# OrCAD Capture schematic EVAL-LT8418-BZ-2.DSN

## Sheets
1 PAGE1: size Custom; note: 100V HALF-BRIDGE GaN DRIVER
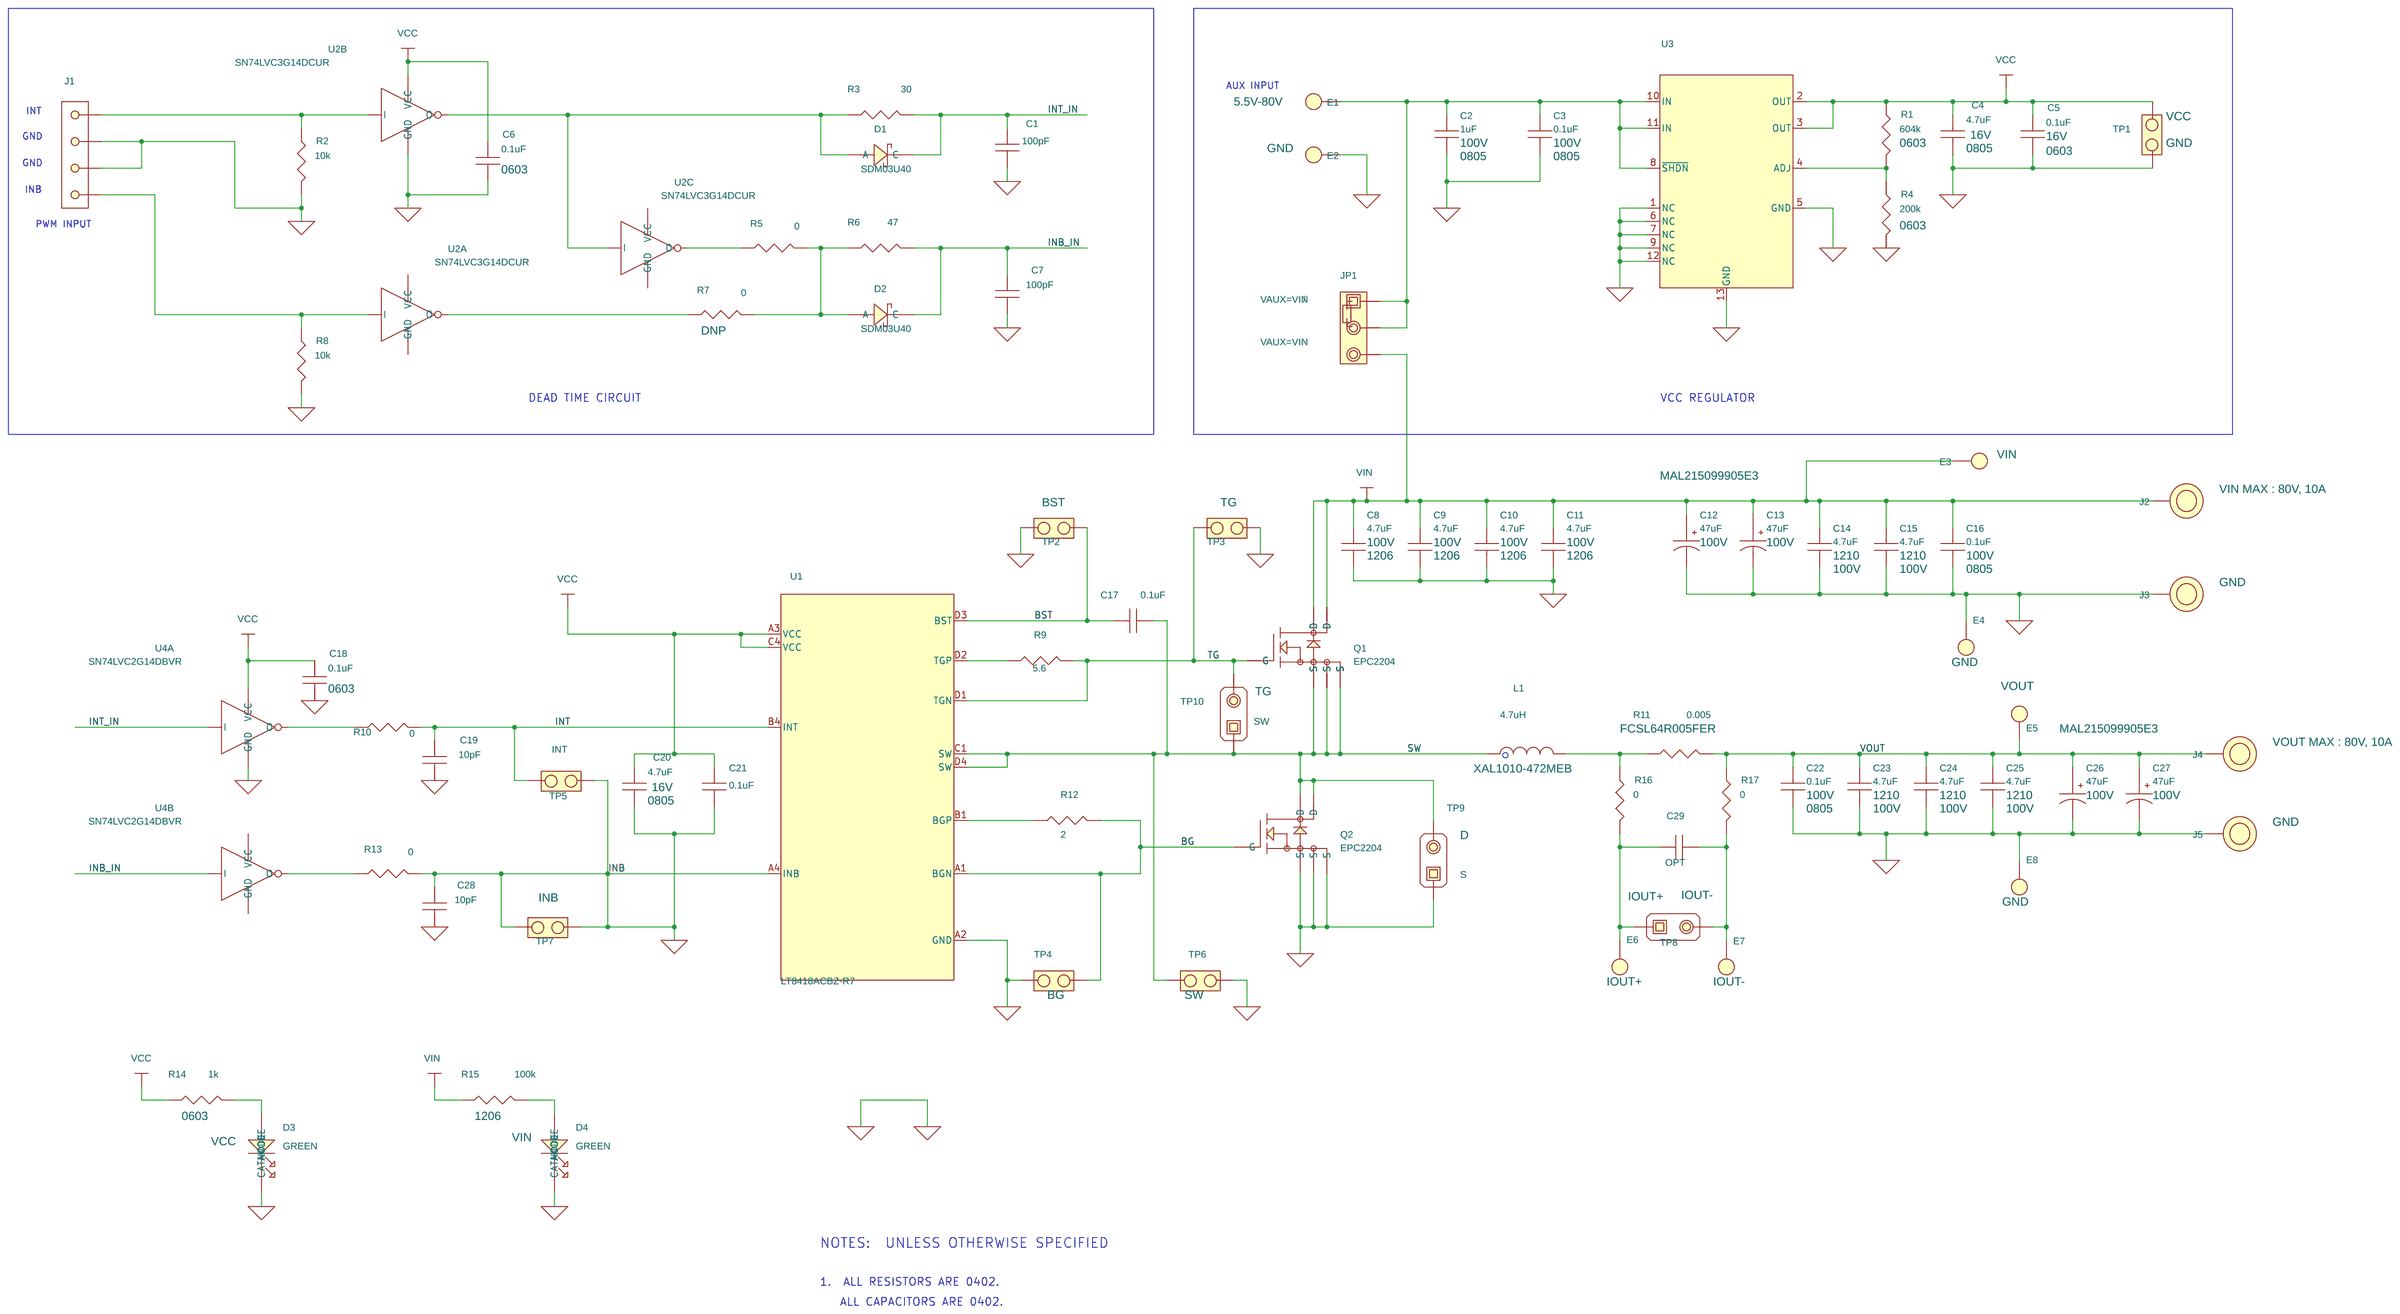
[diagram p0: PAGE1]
2 PAGE2
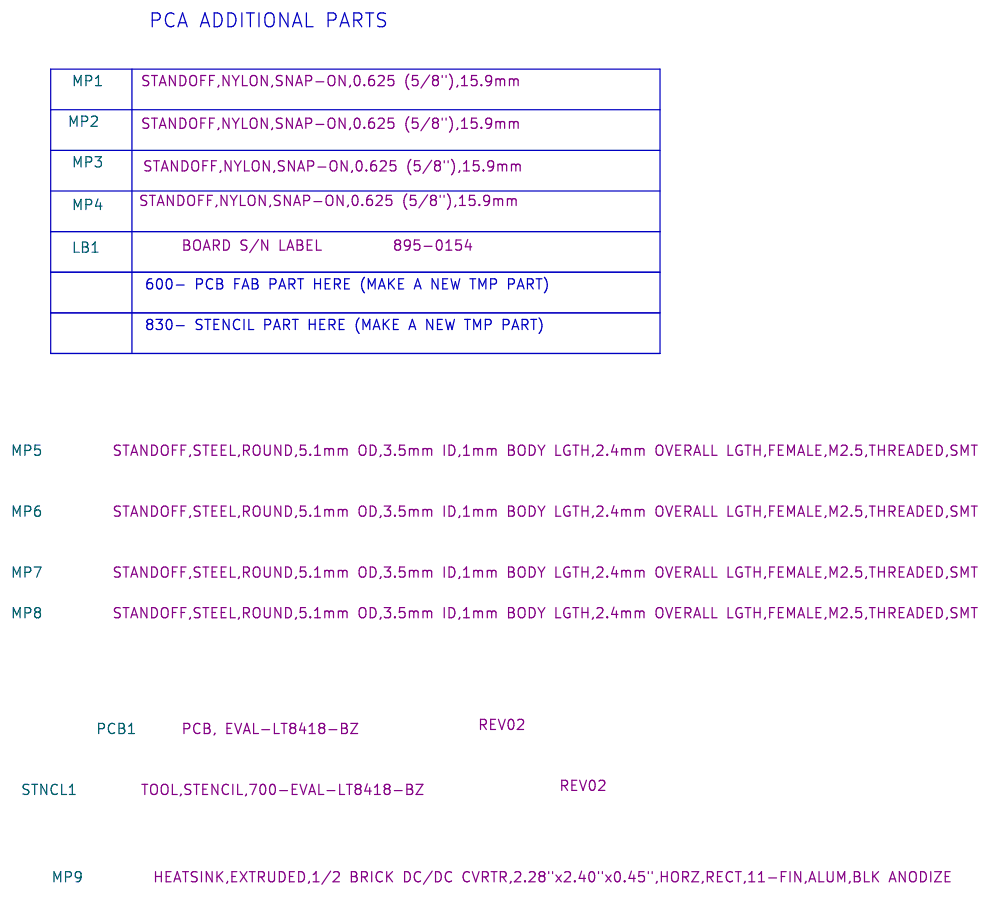
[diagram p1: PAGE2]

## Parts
sheet PAGE1
C1  100pF  [CC0402N]
C2  1uF  [CC0805N]
C3  0.1uF  [CC0805N]
C4  4.7uF  [CC0805N]
C5  0.1uF  [CC0603N]
C6  0.1uF  [CC0603N]
C7  100pF  [CC0402N]
C8  4.7uF  [CC1206N]
C9  4.7uF  [CC1206N]
C10  4.7uF  [CC1206N]
C11  4.7uF  [CC1206N]
C12  47uF  [VISHAY-CASE_CODE-1010]
C13  47uF  [VISHAY-CASE_CODE-1010]
C14  4.7uF  [CC1210N]
C15  4.7uF  [CC1210N]
C16  0.1uF  [CC0805N]
C17  0.1uF  [CC0402N]
C18  0.1uF  [CC0603N]
C19  10pF  [CC0402N]
C20  4.7uF  [CC0805N]
C21  0.1uF  [CC0402N]
C22  0.1uF  [CC0805N]
C23  4.7uF  [CC1210N]
C24  4.7uF  [CC1210N]
C25  4.7uF  [CC1210N]
C26  47uF  [VISHAY-CASE_CODE-1010]
C27  47uF  [VISHAY-CASE_CODE-1010]
C28  10pF  [CC0402N]
C29  OPT  [CC0603N]
D1  SDM03U40  [SOD-523N]
D2  SDM03U40  [SOD-523N]
D3  GREEN  [LED_0805]
D4  GREEN  [LED_0805]
E1  TEST POINT  [MILLMAX2308]
E2  TEST POINT  [MILLMAX2308]
E3  TEST POINT  [MILLMAX2308]
E4  TEST POINT  [MILLMAX2308]
E5  TEST POINT  [MILLMAX2308]
E6  TEST POINT  [MILLMAX2308]
E7  TEST POINT  [MILLMAX2308]
E8  TEST POINT  [MILLMAX2308]
J1  HDR.  [HD1X4-100]
J2  BANANA JACK  [KEY-575-4]
J3  BANANA JACK  [KEY-575-4]
J4  BANANA JACK  [KEY-575-4]
J5  BANANA JACK  [KEY-575-4]
JP1  HDR  [HD1X3-079]
L1  4.7uH  [COILCRAFT-XAL1010]
Q1  EPC2204  [EGAN-EPC2204]
Q2  EPC2204  [EGAN-EPC2204]
R1  604k  [CR0603N]
R2  10k  [CR0402N]
R3  30  [CR0402N]
R4  200k  [CR0603N]
R5  0  [CR0402N]
R6  47  [CR0402N]
R7  0  [CR0402N]
R8  10k  [CR0402N]
R9  5.6  [CR0402N]
R10  0  [CR0402N]
R11  0.005  [OHMITE-FCSL64R005FER]
R12  2  [CR0402N]
R13  0  [CR0402N]
R14  1k  [CR0603N]
R15  100k  [CR1206N]
R16  0  [CR0603N]
R17  0  [CR0603N]
TP1  HDR,SOCKET  [MILL-MAX-310-43-102-41-105000]
TP2  HDR,SOCKET  [MILL-MAX-310-43-102-41-105000]
TP3  HDR,SOCKET  [MILL-MAX-310-43-102-41-105000]
TP4  HDR,SOCKET  [MILL-MAX-310-43-102-41-105000]
TP5  HDR,SOCKET  [MILL-MAX-310-43-102-41-105000]
TP6  HDR,SOCKET  [MILL-MAX-310-43-102-41-105000]
TP7  HDR,SOCKET  [MILL-MAX-310-43-102-41-105000]
TP8  HDR  [SAMTEC-TSM-102-01-L-SV]
TP9  HDR  [SAMTEC-TSM-102-01-L-SV]
TP10  HDR  [SAMTEC-TSM-102-01-L-SV]
U1  LT8418ACBZ-R7  [LTC-CB-12-WLCSP]
U2  SN74LVC3G14DCUR  [TI-DCU]  (sections A,B,C)
U3  LT3012EDE  [LTC-DE-12-1695]
U4  SN74LVC2G14DBVR  [SOT23-6N]  (sections A,B)
XJP1  SHUNT
sheet PAGE2
LB1  LABEL  [895-0154_REV01]
MP1  STANDOFF  [KEYSTONE_8829-8834]
MP2  STANDOFF  [KEYSTONE_8829-8834]
MP3  STANDOFF  [KEYSTONE_8829-8834]
MP4  STANDOFF  [KEYSTONE_8829-8834]
MP5  STANDOFF,STEEL,ROUND
MP6  STANDOFF,STEEL,ROUND
MP7  STANDOFF,STEEL,ROUND
MP8  STANDOFF,STEEL,ROUND
MP9  HEATSINK,EXTRUDED
PCB1  PCB, EVAL-LT8418-BZ
STNCL1  TOOL,STENCIL

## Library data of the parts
C1 C7 = CAP: CAP.,100pF,C0G,50V,5%,0402; CLASS: DISCRETE; Dielectric Type: C0G; FPLIST: CC0402N,CC0402L,CC0402M; Inventory Qty: 62393; Manufacturer: AVX; Manufacturer PN: 04025A101JAT2A; PART_NUMBER: 150-0115; Package Size: 0402; Rated Voltage: 50V; Tolerance: 5%
C2 = CAP: CAP.,1uF,X7S,100V,10%,0805,AEC-Q200,NO SUBS. ALLOWED; CLASS: DISCRETE; Dielectric Type: X7S; FPLIST: CC0805N,CC0805L,CC0805M; Inventory Qty: 11870; Manufacturer: MURATA; Manufacturer PN: GCM21BC72A105KE36L; PART_NUMBER: 150-1770; Package Size: 0805; Rated Voltage: 100V; Temperature Coefficient: X7S; Tolerance: 10%
C3 C16 C22 = CAP: CAP.,0.1uF,X7R,100V,10%,0805; CLASS: DISCRETE; Dielectric Type: X7R; FPLIST: CC0805N,CC0805L,CC0805M; Inventory Qty: 13830; Manufacturer: AVX; Manufacturer PN: 08051C104KAT2A; PART_NUMBER: 150-3062; Package Size: 0805; Rated Voltage: 100V; Tolerance: 10%
C4 C20 = CAP: CAP.,4.7uF,X7R,16V,10%,0805; CLASS: DISCRETE; Dielectric Type: X7R; FPLIST: CC0805N,CC0805L,CC0805M; Inventory Qty: 29263; Manufacturer: AVX; Manufacturer PN: 0805YC475KAT2A; PART_NUMBER: 150-0152; Package Size: 0805; Rated Voltage: 16V; Tolerance: 10%
C5 C6 C18 = CAP: CAP.,0.1uF,X7R,16V,10%,0603; CLASS: DISCRETE; Dielectric Type: X7R; FPLIST: CC0603N,CC0603L,CC0603M; Inventory Qty: 34669; Manufacturer: MURATA; Manufacturer PN: GRM188R71C104KA01D; PART_NUMBER: 150-0018; Package Size: 0603; Package Type: SMD; Rated Voltage: 16V; Tolerance: 10%
C8-C11 = CAP: CAP.,4.7uF,X7S,100V,20%,1206; CLASS: DISCRETE; Dielectric Type: X7S; FPLIST: CC1206N,CC1206L,CC1206M; Inventory Qty: 11240; Manufacturer: AVX; Manufacturer PN: 12061Z475MAT2A; PART_NUMBER: 150-2278; Package Size: 1206; Rated Voltage: 100V; Tolerance: 20%
C12 C13 C26 C27 = CAP_P_ALT: CAP.,47uF,ALUM ELECT,100V,20%,SMD,RADIAL,1012,150 CRZ Series,AEC-Q200; CLASS: DISCRETE; Dielectric Type: ALUM ELECT; Inventory Qty: 0; Manufacturer: VISHAY; Manufacturer PN: MAL215099905E3; PART_NUMBER: 150-1879; Package Size: SMD,RADIAL,1012; Rated Voltage: 100V; Tolerance: 20%
C14 C15 C23-C25 = CAP: CAP.,4.7uF,X7S,100V,10%,1210; CLASS: DISCRETE; Dielectric Type: X7S; FPLIST: CC1210N,CC1210L,CC1210M; Inventory Qty: 8780; Manufacturer: SAMSUNG; Manufacturer PN: CL32Y475KCVZW6E; PART_NUMBER: 150-2270; Package Size: 1210; Package Type: SMD; Rated Voltage: 100V; Temperature Coefficient: X7S; Tolerance: 10%
C17 C21 = CAP: CAP.,0.1uF,X7R,16V,10%,0402; CLASS: DISCRETE; Dielectric Type: X7R; FPLIST: CC0402N,CC0402L,CC0402M; Inventory Qty: 324653; Manufacturer: AVX; Manufacturer PN: 0402YC104KAT2A; PART_NUMBER: 150-2081; Package Size: 0402; Rated Voltage: 16V; Tolerance: 10%
C19 C28 = CAP: CAP.,10pF,C0G,50V,5%,0402; CLASS: DISCRETE; Dielectric Type: C0G; FPLIST: CC0402N,CC0402L,CC0402M; Inventory Qty: 13869; Manufacturer: KEMET; Manufacturer PN: C0402C100J5GAC7867; PART_NUMBER: 150-2069; Package Size: 0402; Rated Voltage: 50V; Tolerance: 5%
C29 = CAP: CAP., OPTION, 0603; CLASS: DISCRETE; FPLIST: CC0603N,CC0603L,CC0603M; PART_NUMBER: 150-3038; Package Size: 0603; Package Type: SMD
D1 D2 = DIODE_SCHOTTKY_A: DIODE,SCHOTTKY,40V,30mA,SOD-523; CLASS: DISCRETE; Inventory Qty: 0; Manufacturer: DIODES INC.; Manufacturer PN: SDM03U40-7; Max Forward Current or Rated Power: 30mA; PART_NUMBER: 210-0555; Package Type: SOD-523; Rated Voltage or Zener Voltage: 40V
D3 = LED: LED,GREEN,WATER-CLEAR,0805; CLASS: DISCRETE; Inventory Qty: 0; Manufacturer: LITE-ON; Manufacturer PN: LTST-C170KGKT; PART_NUMBER: 270-0178; Package Type: 0805; TEXT: VCC
D4 = LED: LED,GREEN,WATER-CLEAR,0805; CLASS: DISCRETE; Inventory Qty: 0; Manufacturer: LITE-ON; Manufacturer PN: LTST-C170KGKT; PART_NUMBER: 270-0178; Package Type: 0805; TEXT: VIN
E1 = TEST_POINT_.156_MILL-MAX_2308: TEST POINT,TURRET,0.064" MTG. HOLE,PCB 0.062" THK; 4th Part Field: 5.5V-80V; CLASS: IO; FPLIST: MILLMAX2308,MILLMAX2308-2; Inventory Qty: 1142083; Manufacturer: MILL-MAX; Manufacturer PN: 2308-2-00-80-00-00-07-0; PART_NUMBER: 260-0004
E2 E4 E8 = TEST_POINT_.156_MILL-MAX_2308: TEST POINT,TURRET,0.064" MTG. HOLE,PCB 0.062" THK; 4th Part Field: GND; CLASS: IO; FPLIST: MILLMAX2308,MILLMAX2308-2; Inventory Qty: 1142083; Manufacturer: MILL-MAX; Manufacturer PN: 2308-2-00-80-00-00-07-0; PART_NUMBER: 260-0004
E3 = TEST_POINT_.156_MILL-MAX_2308: TEST POINT,TURRET,0.064" MTG. HOLE,PCB 0.062" THK; 4th Part Field: VIN; CLASS: IO; FPLIST: MILLMAX2308,MILLMAX2308-2; Inventory Qty: 1142083; Manufacturer: MILL-MAX; Manufacturer PN: 2308-2-00-80-00-00-07-0; PART_NUMBER: 260-0004
E5 = TEST_POINT_.156_MILL-MAX_2308: TEST POINT,TURRET,0.064" MTG. HOLE,PCB 0.062" THK; 4th Part Field: VOUT; CLASS: IO; FPLIST: MILLMAX2308,MILLMAX2308-2; Inventory Qty: 1142083; Manufacturer: MILL-MAX; Manufacturer PN: 2308-2-00-80-00-00-07-0; PART_NUMBER: 260-0004
E6 = TEST_POINT_.156_MILL-MAX_2308: TEST POINT,TURRET,0.064" MTG. HOLE,PCB 0.062" THK; 4th Part Field: IOUT+; CLASS: IO; FPLIST: MILLMAX2308,MILLMAX2308-2; Inventory Qty: 1142083; Manufacturer: MILL-MAX; Manufacturer PN: 2308-2-00-80-00-00-07-0; PART_NUMBER: 260-0004
E7 = TEST_POINT_.156_MILL-MAX_2308: TEST POINT,TURRET,0.064" MTG. HOLE,PCB 0.062" THK; 4th Part Field: IOUT-; CLASS: IO; FPLIST: MILLMAX2308,MILLMAX2308-2; Inventory Qty: 1142083; Manufacturer: MILL-MAX; Manufacturer PN: 2308-2-00-80-00-00-07-0; PART_NUMBER: 260-0004
J1 = HDR1X4: CONN.,HDR.,MALE,1x4,2.54mm,VERT,STR,THT; CLASS: IO; Inventory Qty: 13568; Manufacturer: SAMTEC; Manufacturer PN: TSW-104-07-L-S; PART_NUMBER: 250-0580
J2 = BANANA_KEYSTONE-575-4: CONN.,BANANA JACK,FEMALE,THT,NON-INSULATED,SWAGE,0.218"; 4th Part Field: VIN MAX : 80V, 10A; CLASS: IO; Inventory Qty: 203061; Manufacturer: KEYSTONE; Manufacturer PN: 575-4; PART_NUMBER: 250-0428
J3 J5 = BANANA_KEYSTONE-575-4: CONN.,BANANA JACK,FEMALE,THT,NON-INSULATED,SWAGE,0.218"; 4th Part Field: GND; CLASS: IO; Inventory Qty: 203061; Manufacturer: KEYSTONE; Manufacturer PN: 575-4; PART_NUMBER: 250-0428
J4 = BANANA_KEYSTONE-575-4: CONN.,BANANA JACK,FEMALE,THT,NON-INSULATED,SWAGE,0.218"; 4th Part Field: VOUT MAX : 80V, 10A; CLASS: IO; Inventory Qty: 203061; Manufacturer: KEYSTONE; Manufacturer PN: 575-4; PART_NUMBER: 250-0428
JP1 = 1X3_A: CONN.,HDR,MALE,1x3,2mm,VERT,ST,THT,NO SUBS. ALLOWED; 10th Part Field: /; 11th Part Field: VAUX=VIN; 9th Part Field: VAUX=VIN; CLASS: IO; Inventory Qty: 28997; Manufacturer: Wurth Elektronik; Manufacturer PN: 62000311121; PART_NUMBER: 250-0639
L1 = IND: IND.,4.7uH,PWR,20%,24A,5.7mOHMS,SMD,11.8x10.5x10mm,AEC-Q200; CLASS: DISCRETE; Inventory Qty: 420; Manufacturer: COILCRAFT; Manufacturer PN: XAL1010-472MEB; PART_NUMBER: 200-0382; Package Size: SMD,11.8x10.5x10mm; Tolerance: 20%
Q1 Q2 = EGAN-EPC2204: XSTR.,ENHANCEMENT-MODE GaN FET,100V,29A,2.5x1.5mm; CLASS: DISCRETE; Inventory Qty: 0; Manufacturer: EFFICIENT POWER CONVERSION; PART_NUMBER: 240-0617; Package Size: 2.5mmX1.5mm; Package Type: 2.5x1.5mm; Rated Voltage: 100V
R1 = RES: RES.,604k OHMS,1%,1/10W,0603,AEC-Q200; CLASS: DISCRETE; FPLIST: CR0603N,CR0603L,CR0603M; Inventory Qty: 36156; Manufacturer: VISHAY; Manufacturer PN: CRCW0603604KFKEA; PART_NUMBER: 100-2679; Package Size: 0603; Rated Power: 1/10W; Temperature Coefficient: 100ppm; Tolerance: 1%
R2 R8 = RES: RES.,10k OHMS,1%,1/16W,0402,AEC-Q200; CLASS: DISCRETE; FPLIST: CR0402N,CR0402L,CR0402M; Inventory Qty: 76366; Manufacturer: VISHAY; Manufacturer PN: CRCW040210K0FKED; PART_NUMBER: 100-2545; Package Size: 0402; Rated Power: 1/16W; Temperature Coefficient: 100ppm/C; Tolerance: 1%
R3 = RES: RES.,30 OHMS,1%,1/16W,0402; CLASS: DISCRETE; FPLIST: CR0402N,CR0402L,CR0402M; Inventory Qty: 0; Manufacturer: YAGEO; Manufacturer PN: RC0402FR-0730RL; PART_NUMBER: LOCAL-100-2320; Package Size: 0402; Rated Power: 1/16W; Temperature Coefficient: +/-100; Tolerance: 1%
R4 = RES: RES.,200k OHMS,1%,1/10W,0603; CLASS: DISCRETE; FPLIST: CR0603N,CR0603L,CR0603M; Inventory Qty: 116370; Manufacturer: NIC; Manufacturer PN: NRC06F2003TRF; PART_NUMBER: 100-2378; Package Size: 0603; Rated Power: 1/10W; Temperature Coefficient: 100ppm/C; Tolerance: 1%
R5 R10 R13 = RES: RES.,0 OHM,1/16W,0402; CLASS: DISCRETE; FPLIST: CR0402N,CR0402L,CR0402M; Inventory Qty: 133297; Manufacturer: NIC; Manufacturer PN: NRC04ZOTRF; PART_NUMBER: 100-0025; Package Size: 0402; Rated Power: 1/16W
R6 = RES: RES.,47 OHMS,1%,1/16W,0402; CLASS: DISCRETE; FPLIST: CR0402N,CR0402L,CR0402M; Inventory Qty: 596; Manufacturer: VISHAY; Manufacturer PN: CRCW040247R0FKED; PART_NUMBER: 100-2079; Package Size: 0402; Rated Power: 1/16W; Temperature Coefficient: +/-100PPM; Tolerance: 1%
R7 = RES: RES.,0 OHM,1/16W,0402; CLASS: DISCRETE; FPLIST: CR0402N,CR0402L,CR0402M; Inventory Qty: 133297; Manufacturer: NIC; Manufacturer PN: NRC04ZOTRF; PART_NUMBER: 100-0025; Package Size: 0402; Rated Power: 1/16W; TEXT: DNP
R9 = RES: RES.,5.6 OHMS,1%,1/16W,0402,AEC-Q200; CLASS: DISCRETE; FPLIST: CR0402N,CR0402L,CR0402M; Inventory Qty: 474; Manufacturer: VISHAY; Manufacturer PN: CRCW04025R60FNED; PART_NUMBER: 100-2872; Package Size: 0402; Rated Power: 1/16W; Temperature Coefficient: +/-200ppm; Tolerance: 1%
R11 = RES: RES.,0.005 OHM,1%,2W,2512,LONG-SIDE TERM,METAL,SENSE; CLASS: DISCRETE; Inventory Qty: 0; Manufacturer: Ohmite; Manufacturer PN: FCSL64R005FER; PART_NUMBER: 100-1789; Package Size: 2512,LONG-SIDE TERM; Rated Power: 2W; Temperature Coefficient: +/-50ppm; Tolerance: 1%
R12 = RES: RES.,2 OHMS,1%,1/16W,0402,AEC-Q200; CLASS: DISCRETE; FPLIST: CR0402N,CR0402L,CR0402M; Inventory Qty: 49260; Manufacturer: VISHAY; Manufacturer PN: CRCW04022R00FKED; PART_NUMBER: 100-1452; Package Size: 0402; Rated Power: 1/16W; Temperature Coefficient: +/-100ppm; Tolerance: 1%
R14 = RES: RES.,1k OHM,5%,1/10W,0603,AEC-Q200; CLASS: DISCRETE; FPLIST: CR0603N,CR0603L,CR0603M; Inventory Qty: 86764; Manufacturer: VISHAY; Manufacturer PN: CRCW06031K00JNEA; PART_NUMBER: 100-2534; Package Size: 0603; Rated Power: 1/10W; Temperature Coefficient: 200ppm/C; Tolerance: 5%
R15 = RES: RES.,100k OHMS,5%,1/4W,1206,AEC-Q200; CLASS: DISCRETE; FPLIST: CR1206N,CR1206L,CR1206M; Inventory Qty: 6920; Manufacturer: NIC; Manufacturer PN: NRC12J104TRF; PART_NUMBER: 100-2505; Package Size: 1206; Rated Power: 1/4W; Temperature Coefficient: 200ppm/C; Tolerance: 5%
R16 R17 = RES: RES.,0 OHM,1/10W,0603,AEC-Q200; CLASS: DISCRETE; FPLIST: CR0603N,CR0603L,CR0603M; Inventory Qty: 686486; Manufacturer: VISHAY; Manufacturer PN: CRCW06030000Z0EA; PART_NUMBER: 100-0009; Package Size: 0603; Rated Power: 1/10W
TP1 = 1X2_B: CONN.,HDR,SOCKET,RCPT,FEMALE,1x2,2.54mm,VERT,ST,SMD; 12th Part Field: GND; 9th Part Field: VCC; CLASS: IO; Inventory Qty: 0; Manufacturer: Mill-Max; Manufacturer PN: 310-43-102-41-105000; PART_NUMBER: 250-1048
TP2 = 1X2_B: CONN.,HDR,SOCKET,RCPT,FEMALE,1x2,2.54mm,VERT,ST,SMD; 12th Part Field: GND; 9th Part Field: BST; CLASS: IO; Inventory Qty: 0; Manufacturer: Mill-Max; Manufacturer PN: 310-43-102-41-105000; PART_NUMBER: 250-1048
TP3 = 1X2_B: CONN.,HDR,SOCKET,RCPT,FEMALE,1x2,2.54mm,VERT,ST,SMD; 12th Part Field: GND; 9th Part Field: TG; CLASS: IO; Inventory Qty: 0; Manufacturer: Mill-Max; Manufacturer PN: 310-43-102-41-105000; PART_NUMBER: 250-1048
TP4 = 1X2_B: CONN.,HDR,SOCKET,RCPT,FEMALE,1x2,2.54mm,VERT,ST,SMD; 12th Part Field: GND; 9th Part Field: BG; CLASS: IO; Inventory Qty: 0; Manufacturer: Mill-Max; Manufacturer PN: 310-43-102-41-105000; PART_NUMBER: 250-1048
TP5 = 1X2_B: CONN.,HDR,SOCKET,RCPT,FEMALE,1x2,2.54mm,VERT,ST,SMD; 12th Part Field: GND; 9th Part Field: INT; CLASS: IO; Inventory Qty: 0; Manufacturer: Mill-Max; Manufacturer PN: 310-43-102-41-105000; PART_NUMBER: 250-1048
TP6 = 1X2_B: CONN.,HDR,SOCKET,RCPT,FEMALE,1x2,2.54mm,VERT,ST,SMD; 12th Part Field: GND; 9th Part Field: SW; CLASS: IO; Inventory Qty: 0; Manufacturer: Mill-Max; Manufacturer PN: 310-43-102-41-105000; PART_NUMBER: 250-1048
TP7 = 1X2_B: CONN.,HDR,SOCKET,RCPT,FEMALE,1x2,2.54mm,VERT,ST,SMD; 12th Part Field: GND; 9th Part Field: INB; CLASS: IO; Inventory Qty: 0; Manufacturer: Mill-Max; Manufacturer PN: 310-43-102-41-105000; PART_NUMBER: 250-1048
TP8 = 1X2_A: CONN.,HDR,MALE,1x2,2.54mm,VERT,ST,SMD; CLASS: IO; Inventory Qty: 0; Manufacturer: SAMTEC; Manufacturer PN: TSM-102-01-L-SV; PART_FIELD_01: IOUT+; PART_FIELD_02: IOUT-; PART_NUMBER: local-250-1049
TP9 = 1X2_A: CONN.,HDR,MALE,1x2,2.54mm,VERT,ST,SMD; CLASS: IO; Inventory Qty: 0; Manufacturer: SAMTEC; Manufacturer PN: TSM-102-01-L-SV; PART_FIELD_01: S; PART_FIELD_02: D; PART_NUMBER: local-250-1049
TP10 = 1X2_A: CONN.,HDR,MALE,1x2,2.54mm,VERT,ST,SMD; CLASS: IO; Inventory Qty: 0; Manufacturer: SAMTEC; Manufacturer PN: TSM-102-01-L-SV; PART_FIELD_01: SW; PART_FIELD_02: TG; PART_NUMBER: local-250-1049
U1 = LT8418: IC,100V Half-Bridge GaN Driver,WLCSP-12; CLASS: IC; Inventory Qty: 0; Manufacturer: ANALOG DEVICES; PART_NUMBER: local-LT8418ACBZ-R7; Package Type: WLCSP-12
U2 = TI-SN74LVC3G14DCUR: IC,3CH Schmitt-Trigger Inverter,VSSOP-8; CLASS: IC; Inventory Qty: 0; Manufacturer: TEXAS INSTRUMENTS; PART_NUMBER: 280-0725; Package Size: DUC; Package Type: VSSOP-8
U3 = LT3012-DE: IC,250mA,4V to 80V LDO Linear Reg,DFN-12; CLASS: IC; Inventory Qty: 0; Manufacturer: ANALOG DEVICES; Manufacturer PN: LT3012EDE#PBF; PART_NUMBER: LT3012EDE#PBF; Package Type: DFN-12
U4 = TI-SN74LVC2G14DBVR: IC,Dual Schmitt-Trigger Inverter,SOT23-6; CLASS: IC; FPLIST: SOT23-6N,SOT23-6L,SOT23-6M; Inventory Qty: 1233; Manufacturer: TEXAS INSTRUMENTS; PART_NUMBER: 280-0080; Package Size: sot23-6; Package Type: SOT23-6
XJP1 = SHUNT_2MM_C: CONN.,SHUNT,FEMALE,2-POS,2mm; CLASS: IO; Inventory Qty: 64675; Manufacturer: Wurth Elektronik; Manufacturer PN: 60800213421; PART_NUMBER: 250-0485
LB1 = BLANK_LABEL: LABEL SPEC, DEMO BOARD SERIAL NUMBER; Inventory Qty: 0; Manufacturer: BRADY; Manufacturer PN: THT-96-717-10; PART_FIELD_01: BOARD S/N LABEL; PART_NUMBER: 895-0154
MP1-MP4 = BLANK_PINLESS_MECHANICAL_PART: STANDOFF,NYLON,SNAP-ON,0.625 (5/8"),15.9mm; CLASS: DISCRETE; FPLIST: KEYSTONE_8829-8834,KEYSTONE_8834; Inventory Qty: 185253; Manufacturer: KEYSTONE; Manufacturer PN: 8834; PART_NUMBER: 763-0013
MP5-MP8 = BLANK_MECHANICAL_PART: STANDOFF,STEEL,ROUND,5.1mm OD,3.5mm ID,1mm BODY LGTH,2.4mm OVERALL LGTH,FEMALE,M2.5,THREADED,SMT; CLASS: DISCRETE; Inventory Qty: 0; Manufacturer: WURTH ELEKTRONIK; Manufacturer PN: 9774010151R; PART_NUMBER: 763-0040; Package Size: 1MM
MP9 = BLANK_MECHANICAL_PART: HEATSINK,EXTRUDED,1/2 BRICK DC/DC CVRTR,2.28"x2.40"x0.45",HORZ,RECT,11-FIN,ALUM,BLK ANODIZE; CLASS: DISCRETE; Inventory Qty: 0; Manufacturer: Wakefield-Vette; Manufacturer PN: 527-45AB; PART_NUMBER: 930-0011
PCB1 = BLANK_PCB_PART: BOM Notes: REV02; CLASS: DISCRETE; Inventory Qty: 0; Manufacturer: ADI APPROVED SUPPLIER; Manufacturer PN: 600-EVAL-LT8418-BZ; PART_NUMBER: LOCAL-600-EVAL-LT8418-BZ
STNCL1 = BLANK_STENCIL_PART: TOOL,STENCIL,700-EVAL-LT8418-BZ; BOM Notes: REV02; CLASS: DISCRETE; Inventory Qty: 0; Manufacturer: ADI APPROVED SUPPLIER; Manufacturer PN: 830-EVAL-LT8418-BZ; PART_NUMBER: LOCAL-830-EVAL-LT8418-BZ

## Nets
GND: C1.2 C2.2 C3.2 C4.2 C5.2 C6.2 C7.2 C8.2 C9.2 C10.2 C11.2 C12.2 C13.2 C14.2 C15.2 C16.2 C18.2 C19.2 C20.2 C21.2 C22.2 C23.2 C24.2 C25.2 C26.2 C27.2 C28.2 D3.1(CATHODE) D4.1(CATHODE) E2.1(A) E4.1(A) E8.1(A) J1.2 J1.3 J3.1 J5.1 Q2.2(S) Q2.4(S) Q2.6(S) R2.2 R4.2 R8.2 TP1.2 TP2.1 TP3.1 TP4.2 TP5.1 TP6.2 TP7.1 TP9.1 U1.A2(GND) U2.4(GND) U3.1(NC) U3.5(GND) U3.6(NC) U3.7(NC) U3.9(NC) U3.12(NC) U3.13(GND) U4.2(GND)
VCC: C4.1 C5.1 C6.1 C18.1 C20.1 C21.1 R1.1 R14.1 TP1.1 U1.A3(VCC) U1.C4(VCC) U2.8(VCC) U3.2(OUT) U3.3(OUT) U4.5(VCC)
VIN: C8.1 C9.1 C10.1 C11.1 C12.1 C13.1 C14.1 C15.1 C16.1 E3.1(A) J2.1 JP1.3 Q1.3(D) Q1.5(D) R15.1
BG: Q2.1(G) R12.2 TP4.1 U1.A1(BGN)
BST: C17.1 TP2.2 U1.D3(BST)
INB: C28.1 R13.2 TP7.2 U1.A4(INB)
INB_IN: C7.1 D2.1(C) R6.2 U4.3(I)
INT: C19.1 R10.2 TP5.2 U1.B4(INT)
INT_IN: C1.1 D1.1(C) R3.2 U4.1(I)
SW: C17.2 L1.1 Q1.2(S) Q1.4(S) Q1.6(S) Q2.3(D) Q2.5(D) TP6.1 TP9.2 TP10.1 U1.C1(SW) U1.D4(SW)
TG: Q1.1(G) R9.2 TP3.2 TP10.2 U1.D1(TGN)
VOUT: C22.1 C23.1 C24.1 C25.1 C26.1 C27.1 E5.1(A) J4.1 R11.2 R17.1
N00407: C2.1 C3.1 E1.1(A) JP1.1 JP1.2 U3.8(~{SHDN}) U3.10(IN) U3.11(IN)
N00783: R1.2 R4.1 U3.4(ADJ)
N21945: J1.1 R2.1 U2.3(I)
N22596: J1.4 R8.1 U2.1(I)
N23138: D1.2(A) R3.1 U2.5(O) U2.6(I)
N23381: R5.1 U2.2(O)
N23411: D2.2(A) R5.2 R6.1 R7.2
N24352: R7.1 U2.7(O)
N25048: R10.1 U4.6(O)
N25052: R13.1 U4.4(O)
N26468: D3.2(ANODE) R14.2
N26608: D4.2(ANODE) R15.2
N27605: R9.1 U1.D2(TGP)
N28212: R12.1 U1.B1(BGP)
N29956: L1.2 R11.1 R16.1
N16625920: C29.1 E6.1(A) R16.2 TP8.1
N16625935: C29.2 E7.1(A) R17.2 TP8.2

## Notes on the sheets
sheet 1
- AUX INPUT
- INT
- GND
- GND
- INB
- PWM INPUT
- DEAD TIME CIRCUIT
- VCC REGULATOR
- NOTES:  UNLESS OTHERWISE SPECIFIED
- 1.  ALL RESISTORS ARE 0402.
- ALL CAPACITORS ARE 0402.
sheet 2
- PCA ADDITIONAL PARTS
- 600- PCB FAB PART HERE (MAKE A NEW TMP PART)
- 830- STENCIL PART HERE (MAKE A NEW TMP PART)
